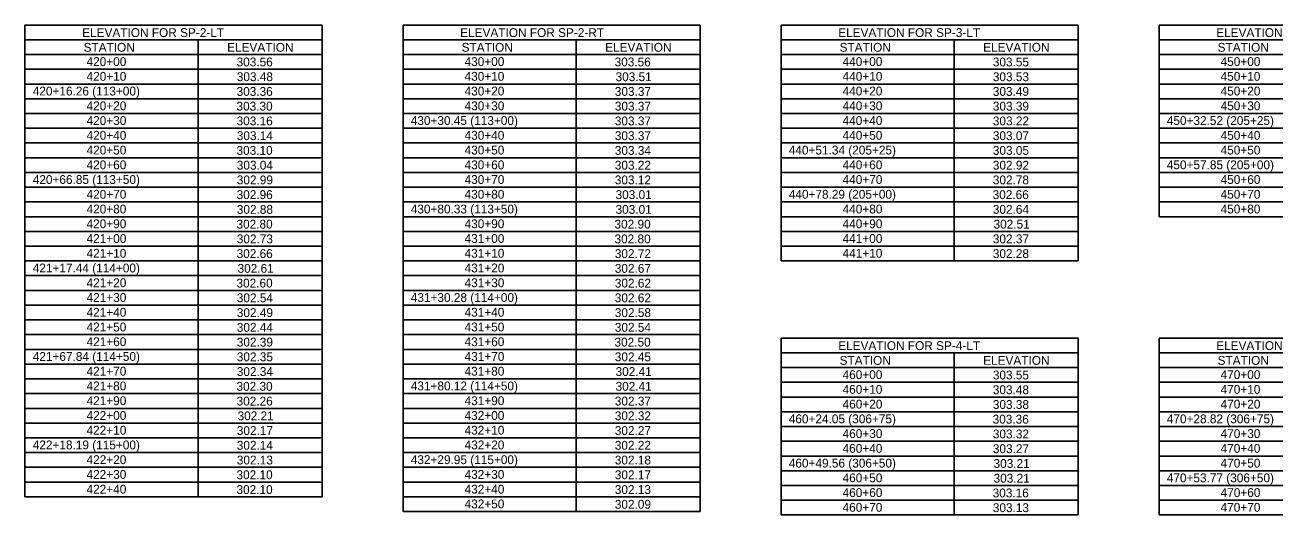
# Model space of a CAD drawing. Extents: x 916322 to 917003, y 328419 to 328887.
# Drawn here: x 916321.6 to 916763.4, y 328419.1 to 328592.1 of the extents above; entities that cross this region are included whole.
import ezdxf

# ---------------------------------------------------------------- set-up
doc = ezdxf.new("R2010")
doc.units = 0
doc.layers.add('ANNOTATION', color=7, linetype='Continuous')

msp = doc.modelspace()

# ---------------------------------------------------------------- linework, layer by layer
at = {"layer": 'ANNOTATION'}
for p, q in [((916321.61, 328592.14), (916426.61, 328592.14)), ((916321.61, 328425.47), (916321.61, 328592.14)), ((916426.61, 328425.47), (916426.61, 328592.14)), ((916455.22, 328592.14), (916560.22, 328592.14)), ((916455.22, 328420.26), (916455.22, 328592.14)), ((916560.22, 328420.26), (916560.22, 328592.14)), ((916588.83, 328592.14), (916693.83, 328592.14)), ((916588.83, 328508.8), (916588.83, 328592.14)), ((916693.83, 328508.8), (916693.83, 328592.14)), ((916722.44, 328592.14), (916827.44, 328592.14)), ((916722.44, 328524.43), (916722.44, 328592.14)), ((916321.61, 328586.93), (916426.61, 328586.93)), ((916382.81, 328425.47), (916382.81, 328586.93)), ((916455.22, 328586.93), (916560.22, 328586.93)), ((916516.42, 328420.26), (916516.42, 328586.93)), ((916588.83, 328586.93), (916693.83, 328586.93)), ((916650.03, 328508.8), (916650.03, 328586.93)), ((916722.44, 328586.93), (916827.44, 328586.93)), ((916321.61, 328581.72), (916426.61, 328581.72)), ((916455.22, 328581.72), (916560.22, 328581.72)), ((916588.83, 328581.72), (916693.83, 328581.72)), ((916722.44, 328581.72), (916827.44, 328581.72)), ((916321.61, 328576.51), (916426.61, 328576.51)), ((916455.22, 328576.51), (916560.22, 328576.51)), ((916588.83, 328576.51), (916693.83, 328576.51)), ((916722.44, 328576.51), (916827.44, 328576.51)), ((916321.61, 328571.3), (916426.61, 328571.3)), ((916455.22, 328571.3), (916560.22, 328571.3)), ((916588.83, 328571.3), (916693.83, 328571.3)), ((916722.44, 328571.3), (916827.44, 328571.3)), ((916321.61, 328566.1), (916426.61, 328566.1)), ((916455.22, 328566.1), (916560.22, 328566.1)), ((916588.83, 328566.1), (916693.83, 328566.1)), ((916722.44, 328566.1), (916827.44, 328566.1)), ((916321.61, 328560.89), (916426.61, 328560.89)), ((916455.22, 328560.89), (916560.22, 328560.89)), ((916588.83, 328560.89), (916693.83, 328560.89)), ((916722.44, 328560.89), (916827.44, 328560.89)), ((916321.61, 328555.68), (916426.61, 328555.68)), ((916455.22, 328555.68), (916560.22, 328555.68)), ((916588.83, 328555.68), (916693.83, 328555.68)), ((916722.44, 328555.68), (916827.44, 328555.68)), ((916321.61, 328550.47), (916426.61, 328550.47)), ((916455.22, 328550.47), (916560.22, 328550.47)), ((916588.83, 328550.47), (916693.83, 328550.47)), ((916722.44, 328550.47), (916827.44, 328550.47)), ((916321.61, 328545.26), (916426.61, 328545.26)), ((916455.22, 328545.26), (916560.22, 328545.26)), ((916588.83, 328545.26), (916693.83, 328545.26)), ((916722.44, 328545.26), (916827.44, 328545.26)), ((916321.61, 328540.05), (916426.61, 328540.05)), ((916455.22, 328540.05), (916560.22, 328540.05)), ((916588.83, 328540.05), (916693.83, 328540.05)), ((916722.44, 328540.05), (916827.44, 328540.05)), ((916321.61, 328534.85), (916426.61, 328534.85)), ((916455.22, 328534.85), (916560.22, 328534.85)), ((916588.83, 328534.85), (916693.83, 328534.85)), ((916722.44, 328534.85), (916827.44, 328534.85)), ((916321.61, 328529.64), (916426.61, 328529.64)), ((916455.22, 328529.64), (916560.22, 328529.64)), ((916588.83, 328529.64), (916693.83, 328529.64)), ((916722.44, 328529.64), (916827.44, 328529.64)), ((916321.61, 328524.43), (916426.61, 328524.43)), ((916455.22, 328524.43), (916560.22, 328524.43)), ((916588.83, 328524.43), (916693.83, 328524.43)), ((916722.44, 328524.43), (916827.44, 328524.43)), ((916321.61, 328519.22), (916426.61, 328519.22)), ((916455.22, 328519.22), (916560.22, 328519.22)), ((916588.83, 328519.22), (916693.83, 328519.22)), ((916321.61, 328514.01), (916426.61, 328514.01)), ((916455.22, 328514.01), (916560.22, 328514.01)), ((916588.83, 328514.01), (916693.83, 328514.01)), ((916321.61, 328508.8), (916426.61, 328508.8)), ((916455.22, 328508.8), (916560.22, 328508.8)), ((916588.83, 328508.8), (916693.83, 328508.8)), ((916321.61, 328503.6), (916426.61, 328503.6)), ((916455.22, 328503.6), (916560.22, 328503.6)), ((916321.61, 328498.39), (916426.61, 328498.39)), ((916455.22, 328498.39), (916560.22, 328498.39)), ((916321.61, 328493.18), (916426.61, 328493.18)), ((916455.22, 328493.18), (916560.22, 328493.18)), ((916321.61, 328487.97), (916426.61, 328487.97)), ((916455.22, 328487.97), (916560.22, 328487.97)), ((916321.61, 328482.76), (916426.61, 328482.76)), ((916455.22, 328482.76), (916560.22, 328482.76)), ((916588.83, 328481.55), (916693.83, 328481.55)), ((916588.83, 328419.05), (916588.83, 328481.55)), ((916693.83, 328419.05), (916693.83, 328481.55)), ((916722.44, 328481.55), (916827.44, 328481.55)), ((916722.44, 328419.05), (916722.44, 328481.55)), ((916321.61, 328477.55), (916426.61, 328477.55)), ((916455.22, 328477.55), (916560.22, 328477.55)), ((916588.83, 328476.35), (916693.83, 328476.35)), ((916650.03, 328419.05), (916650.03, 328476.35)), ((916722.44, 328476.35), (916827.44, 328476.35)), ((916321.61, 328472.35), (916426.61, 328472.35)), ((916455.22, 328472.35), (916560.22, 328472.35)), ((916588.83, 328471.14), (916693.83, 328471.14)), ((916722.44, 328471.14), (916827.44, 328471.14)), ((916321.61, 328467.14), (916426.61, 328467.14)), ((916455.22, 328467.14), (916560.22, 328467.14)), ((916588.83, 328465.93), (916693.83, 328465.93)), ((916722.44, 328465.93), (916827.44, 328465.93)), ((916321.61, 328461.93), (916426.61, 328461.93)), ((916455.22, 328461.93), (916560.22, 328461.93)), ((916588.83, 328460.72), (916693.83, 328460.72)), ((916722.44, 328460.72), (916827.44, 328460.72)), ((916321.61, 328456.72), (916426.61, 328456.72)), ((916455.22, 328456.72), (916560.22, 328456.72)), ((916588.83, 328455.51), (916693.83, 328455.51)), ((916722.44, 328455.51), (916827.44, 328455.51)), ((916321.61, 328451.51), (916426.61, 328451.51)), ((916455.22, 328451.51), (916560.22, 328451.51)), ((916588.83, 328450.3), (916693.83, 328450.3)), ((916722.44, 328450.3), (916827.44, 328450.3)), ((916321.61, 328446.3), (916426.61, 328446.3)), ((916455.22, 328446.3), (916560.22, 328446.3)), ((916588.83, 328445.1), (916693.83, 328445.1)), ((916722.44, 328445.1), (916827.44, 328445.1)), ((916321.61, 328441.1), (916426.61, 328441.1)), ((916455.22, 328441.1), (916560.22, 328441.1)), ((916588.83, 328439.89), (916693.83, 328439.89)), ((916722.44, 328439.89), (916827.44, 328439.89)), ((916321.61, 328435.89), (916426.61, 328435.89)), ((916455.22, 328435.89), (916560.22, 328435.89)), ((916588.83, 328434.68), (916693.83, 328434.68)), ((916722.44, 328434.68), (916827.44, 328434.68)), ((916321.61, 328430.68), (916426.61, 328430.68)), ((916455.22, 328430.68), (916560.22, 328430.68)), ((916321.61, 328425.47), (916426.61, 328425.47)), ((916455.22, 328425.47), (916560.22, 328425.47)), ((916588.83, 328429.47), (916693.83, 328429.47)), ((916722.44, 328429.47), (916827.44, 328429.47)), ((916588.83, 328424.26), (916693.83, 328424.26)), ((916722.44, 328424.26), (916827.44, 328424.26)), ((916455.22, 328420.26), (916560.22, 328420.26)), ((916588.83, 328419.05), (916693.83, 328419.05)), ((916722.44, 328419.05), (916827.44, 328419.05))]:
    msp.add_line(p, q, dxfattribs=at)

# ---------------------------------------------------------------- texts
for s, p in [('ELEVATION FOR SP-2-LT', (916341.82, 328587.89)), ('ELEVATION FOR SP-2-RT', (916475.43, 328587.89)), ('ELEVATION FOR SP-3-LT', (916609.04, 328587.89)), ('ELEVATION FOR SP-3-RT', (916742.65, 328587.89)), ('STATION', (916342.31, 328582.69)), ('ELEVATION', (916393.05, 328582.69)), ('STATION', (916475.92, 328582.69)), ('ELEVATION', (916526.66, 328582.69)), ('STATION', (916609.53, 328582.69)), ('ELEVATION', (916660.27, 328582.69)), ('STATION', (916743.14, 328582.69)), ('ELEVATION FOR SP-4-LT', (916609.04, 328477.31)), ('ELEVATION FOR SP-4-RT', (916742.65, 328477.31)), ('STATION', (916609.53, 328472.1)), ('ELEVATION', (916660.27, 328472.1)), ('STATION', (916743.14, 328472.1))]:
    msp.add_text(s, height=3.125, rotation=360, dxfattribs=at).set_placement(p)
for s, p in [('420+00', (916343.37, 328577.65)), ('303.56', (916396.4, 328577.52)), ('430+00', (916476.98, 328577.65)), ('303.56', (916530.01, 328577.52)), ('440+00', (916610.59, 328577.65)), ('303.55', (916663.69, 328577.52)), ('450+00', (916744.2, 328577.65)), ('420+10', (916343.37, 328572.44)), ('430+10', (916476.98, 328572.44)), ('440+10', (916610.59, 328572.44)), ('450+10', (916744.2, 328572.44)), ('303.48', (916396.47, 328572.31)), ('303.51', (916530.35, 328572.31)), ('303.53', (916663.69, 328572.31)), ('420+16.26 (113+00)', (916324.35, 328567.24)), ('303.36', (916396.4, 328567.11)), ('430+20', (916476.98, 328567.24)), ('303.37', (916530.08, 328567.11)), ('440+20', (916610.59, 328567.24)), ('303.49', (916663.69, 328567.11)), ('450+20', (916744.2, 328567.24)), ('420+20', (916343.37, 328562.03)), ('303.30', (916396.36, 328561.9)), ('430+30', (916476.98, 328562.03)), ('303.37', (916530.08, 328561.9)), ('440+30', (916610.59, 328562.03)), ('303.39', (916663.69, 328561.9)), ('450+30', (916744.2, 328562.03)), ('420+30', (916343.37, 328556.82)), ('303.16', (916396.4, 328556.69)), ('430+30.45 (113+00)', (916457.96, 328556.82)), ('303.37', (916530.08, 328556.69)), ('440+40', (916610.59, 328556.82)), ('303.22', (916663.69, 328556.69)), ('450+32.52 (205+25)', (916725.18, 328556.82)), ('420+40', (916343.37, 328551.61)), ('303.14', (916396.47, 328551.48)), ('430+40', (916476.98, 328551.61)), ('303.37', (916530.08, 328551.48)), ('440+50', (916610.59, 328551.61)), ('303.07', (916663.69, 328551.48)), ('450+40', (916744.2, 328551.61)), ('420+50', (916343.37, 328546.4)), ('303.10', (916396.36, 328546.27)), ('430+50', (916476.98, 328546.4)), ('303.34', (916530.08, 328546.27)), ('440+51.34 (205+25)', (916591.57, 328546.4)), ('303.05', (916663.69, 328546.27)), ('450+50', (916744.2, 328546.4)), ('420+60', (916343.37, 328541.19)), ('303.04', (916396.47, 328541.06)), ('430+60', (916476.98, 328541.19)), ('303.22', (916530.08, 328541.06)), ('440+60', (916610.59, 328541.19)), ('302.92', (916663.69, 328541.06)), ('450+57.85 (205+00)', (916725.18, 328541.19)), ('420+66.85 (113+50)', (916324.35, 328535.99)), ('302.99', (916396.47, 328535.86)), ('430+70', (916476.98, 328535.99)), ('303.12', (916530.08, 328535.86)), ('440+70', (916610.59, 328535.99)), ('302.78', (916663.69, 328535.86)), ('450+60', (916744.2, 328535.99)), ('420+70', (916343.37, 328530.78)), ('302.96', (916396.4, 328530.65)), ('430+80', (916476.98, 328530.78)), ('303.01', (916530.35, 328530.65)), ('440+78.29 (205+00)', (916591.57, 328530.78)), ('302.66', (916663.62, 328530.65)), ('450+70', (916744.2, 328530.78)), ('420+80', (916343.37, 328525.57)), ('302.88', (916396.47, 328525.44)), ('430+80.33 (113+50)', (916457.96, 328525.57)), ('303.01', (916530.35, 328525.44)), ('440+80', (916610.59, 328525.57)), ('302.64', (916663.69, 328525.44)), ('450+80', (916744.2, 328525.57)), ('420+90', (916343.37, 328520.36)), ('302.80', (916396.36, 328520.23)), ('430+90', (916476.98, 328520.36)), ('302.90', (916529.97, 328520.23)), ('440+90', (916610.59, 328520.36)), ('302.51', (916663.95, 328520.23)), ('421+00', (916343.37, 328515.15)), ('302.73', (916396.47, 328515.02)), ('431+00', (916476.98, 328515.15)), ('302.80', (916529.97, 328515.02)), ('441+00', (916610.59, 328515.15)), ('302.37', (916663.69, 328515.02)), ('421+10', (916343.37, 328509.94)), ('302.66', (916396.4, 328509.81)), ('431+10', (916476.98, 328509.94)), ('302.72', (916530.08, 328509.81)), ('441+10', (916610.59, 328509.94)), ('302.28', (916663.69, 328509.81)), ('421+17.44 (114+00)', (916324.35, 328504.74)), ('302.61', (916396.74, 328504.61)), ('431+20', (916476.98, 328504.74)), ('302.67', (916530.08, 328504.61)), ('421+20', (916343.37, 328499.53)), ('302.60', (916396.36, 328499.4)), ('431+30', (916476.98, 328499.53)), ('302.62', (916530.08, 328499.4)), ('421+30', (916343.37, 328494.32)), ('302.54', (916396.47, 328494.19)), ('431+30.28 (114+00)', (916457.96, 328494.32)), ('302.62', (916530.08, 328494.19)), ('421+40', (916343.37, 328489.11)), ('302.49', (916396.47, 328488.98)), ('431+40', (916476.98, 328489.11)), ('302.58', (916530.08, 328488.98)), ('421+50', (916343.37, 328483.9)), ('302.44', (916396.47, 328483.77)), ('431+50', (916476.98, 328483.9)), ('302.54', (916530.08, 328483.77)), ('421+60', (916343.37, 328478.69)), ('302.39', (916396.47, 328478.56)), ('431+60', (916476.98, 328478.69)), ('302.50', (916529.97, 328478.56)), ('421+67.84 (114+50)', (916324.35, 328473.49)), ('302.35', (916396.47, 328473.36)), ('431+70', (916476.98, 328473.49)), ('302.45', (916530.08, 328473.36)), ('421+70', (916343.37, 328468.28)), ('302.34', (916396.47, 328468.15)), ('431+80', (916476.98, 328468.28)), ('302.41', (916530.35, 328468.15)), ('460+00', (916610.59, 328467.07)), ('303.55', (916663.69, 328466.94)), ('470+00', (916744.2, 328467.07)), ('421+80', (916343.37, 328463.07)), ('302.30', (916396.36, 328462.94)), ('431+80.12 (114+50)', (916457.96, 328463.07)), ('302.41', (916530.35, 328462.94)), ('421+90', (916343.37, 328457.86)), ('302.26', (916396.4, 328457.73)), ('431+90', (916476.98, 328457.86)), ('302.37', (916530.08, 328457.73)), ('460+10', (916610.59, 328461.86)), ('303.48', (916663.69, 328461.73)), ('470+10', (916744.2, 328461.86)), ('460+20', (916610.59, 328456.65)), ('303.38', (916663.69, 328456.52)), ('470+20', (916744.2, 328456.65)), ('422+00', (916343.37, 328452.65)), ('302.21', (916396.74, 328452.52)), ('432+00', (916476.98, 328452.65)), ('302.32', (916530.08, 328452.52)), ('460+24.05 (306+75)', (916591.57, 328451.45)), ('303.36', (916663.62, 328451.32)), ('470+28.82 (306+75)', (916725.18, 328451.45)), ('422+10', (916343.37, 328447.44)), ('302.17', (916396.47, 328447.31)), ('432+10', (916476.98, 328447.44)), ('302.27', (916530.08, 328447.31)), ('460+30', (916610.59, 328446.24)), ('303.32', (916663.69, 328446.11)), ('470+30', (916744.2, 328446.24)), ('422+18.19 (115+00)', (916324.35, 328442.24)), ('302.14', (916396.47, 328442.11)), ('432+20', (916476.98, 328442.24)), ('302.22', (916530.08, 328442.11)), ('460+40', (916610.59, 328441.03)), ('303.27', (916663.69, 328440.9)), ('470+40', (916744.2, 328441.03)), ('422+20', (916343.37, 328437.03)), ('302.13', (916396.47, 328436.9)), ('432+29.95 (115+00)', (916457.96, 328437.03)), ('302.18', (916530.08, 328436.9)), ('460+49.56 (306+50)', (916591.57, 328435.82)), ('303.21', (916663.95, 328435.69)), ('470+50', (916744.2, 328435.82)), ('422+30', (916343.37, 328431.82)), ('302.10', (916396.36, 328431.69)), ('432+30', (916476.98, 328431.82)), ('302.17', (916530.08, 328431.69)), ('422+40', (916343.37, 328426.61)), ('432+40', (916476.98, 328426.61)), ('460+50', (916610.59, 328430.61)), ('303.21', (916663.95, 328430.48)), ('470+53.77 (306+50)', (916725.18, 328430.61)), ('302.10', (916396.36, 328426.48)), ('302.13', (916530.08, 328426.48)), ('460+60', (916610.59, 328425.4)), ('303.16', (916663.62, 328425.27)), ('470+60', (916744.2, 328425.4)), ('432+50', (916476.98, 328421.4)), ('302.09', (916530.08, 328421.27)), ('460+70', (916610.59, 328420.2)), ('303.13', (916663.69, 328420.07)), ('470+70', (916744.2, 328420.2))]:
    msp.add_text(s, height=3.125, dxfattribs=at).set_placement(p)

doc.saveas('drawing.dxf')
